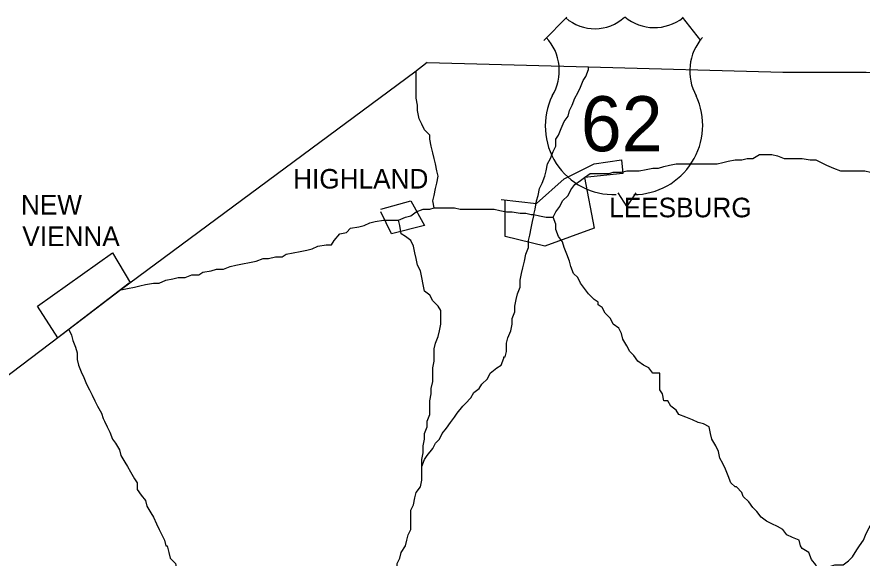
# Model space of a CAD drawing. Extents: x 0 to 34, y 0 to 22.
# Drawn here: x 3.578 to 4.42, y 18.911 to 19.45 of the extents above; entities that cross this region are included whole.
import ezdxf

# ---------------------------------------------------------------- set-up
doc = ezdxf.new("R2010")
doc.units = 0
doc.layers.add('Default', color=7, linetype='Continuous')

msp = doc.modelspace()

# ---------------------------------------------------------------- linework, layer by layer
at = {"layer": 'Default'}
for p, q in [((4.12627, 19.44935), (4.10326, 19.42634)), ((4.25971, 19.42634), (4.24131, 19.44935)), ((4.14382, 19.28966), (4.14928, 19.29375)), ((4.17689, 19.27449), (4.18609, 19.26069)), ((4.18609, 19.26069), (4.19529, 19.27449))]:
    msp.add_line(p, q, dxfattribs=at)
for points in [[(3.98703, 19.40419), (3.97476, 19.39464), (3.68162, 19.17786), (3.62981, 19.13832), (3.40076, 18.96516)], [(3.98703, 19.40419), (4.14791, 19.4001), (4.34152, 19.39464), (4.42469, 19.39464), (4.726, 19.38919), (4.75327, 19.38919)], [(3.99385, 19.25966), (3.99248, 19.26648), (3.99385, 19.27193), (3.99521, 19.27875), (3.99657, 19.2842), (3.99794, 19.29102), (3.99657, 19.29648), (3.99521, 19.30329), (3.99385, 19.30875), (3.99248, 19.3142), (3.99112, 19.32102), (3.98976, 19.32783), (3.98976, 19.33192), (3.9843, 19.33738), (3.98158, 19.34283), (3.97885, 19.34829), (3.97749, 19.35647), (3.97749, 19.36192), (3.97612, 19.36874), (3.97612, 19.37419), (3.97612, 19.38101), (3.97612, 19.38782), (3.97612, 19.39464), (3.97612, 19.39601), (3.97612, 19.39601)], [(4.09338, 19.25285), (4.09474, 19.2583), (4.0961, 19.26648), (4.09747, 19.27193), (4.09883, 19.27875), (4.10156, 19.2842), (4.10428, 19.29102), (4.10565, 19.29648), (4.10701, 19.30329), (4.10974, 19.30875), (4.11247, 19.31556), (4.11519, 19.32102), (4.11519, 19.32783), (4.11792, 19.33192), (4.12065, 19.33874), (4.12337, 19.34556), (4.12746, 19.35101), (4.12883, 19.35647), (4.13155, 19.36192), (4.13428, 19.36874), (4.13701, 19.37419), (4.13973, 19.37964), (4.14246, 19.38646), (4.14519, 19.39055), (4.14791, 19.39737), (4.14791, 19.4001)], [(4.21745, 19.2992), (4.2229, 19.30057), (4.22836, 19.30193), (4.23517, 19.30329), (4.24199, 19.30329), (4.24881, 19.30329), (4.25426, 19.30329), (4.26244, 19.30329), (4.2679, 19.30329), (4.27608, 19.30329), (4.28153, 19.30466), (4.28698, 19.30602), (4.2938, 19.30738), (4.30062, 19.30738), (4.30607, 19.30875), (4.31152, 19.30875), (4.31834, 19.31284), (4.32516, 19.31284), (4.33061, 19.31284), (4.33607, 19.31147), (4.34288, 19.30875), (4.34834, 19.30875), (4.3497, 19.30875)], [(4.3497, 19.30875), (4.35515, 19.30875), (4.36061, 19.30875), (4.36879, 19.30738), (4.37424, 19.30738), (4.3797, 19.30466), (4.38515, 19.30193), (4.39197, 19.2992), (4.39878, 19.29648), (4.40424, 19.29648), (4.40969, 19.29648), (4.41651, 19.29648), (4.42333, 19.29648), (4.42878, 19.29511), (4.4356, 19.29102), (4.44241, 19.28966), (4.44923, 19.28829), (4.45468, 19.28693), (4.4615, 19.28693), (4.46695, 19.28829), (4.46832, 19.28829)], [(4.06066, 19.26784), (4.0961, 19.26375), (4.12337, 19.28829), (4.15337, 19.30329), (4.18064, 19.30738), (4.182, 19.29375), (4.14382, 19.28966), (4.15337, 19.23921), (4.10428, 19.22149), (4.06475, 19.23103), (4.06475, 19.26648)], [(4.11247, 19.25012), (4.11519, 19.25557), (4.11928, 19.26103), (4.12201, 19.26648), (4.12746, 19.27193), (4.13019, 19.27739), (4.13428, 19.28284), (4.13973, 19.28693), (4.14382, 19.28966), (4.14928, 19.29375), (4.15473, 19.29375), (4.16155, 19.29375), (4.16837, 19.29375), (4.17246, 19.29511), (4.18064, 19.29511), (4.18609, 19.29648), (4.19427, 19.29648), (4.19836, 19.29648), (4.20518, 19.29784), (4.212, 19.2992), (4.21609, 19.2992), (4.21745, 19.2992)], [(3.94067, 19.2583), (3.97067, 19.26648), (3.9843, 19.24194), (3.95158, 19.23376), (3.94067, 19.25557)], [(3.9584, 19.24739), (3.96522, 19.25012), (3.97067, 19.25148), (3.97612, 19.25557), (3.98294, 19.2583), (3.98976, 19.2583), (3.99385, 19.25966), (3.99385, 19.25966)], [(3.9584, 19.24739), (3.96522, 19.25012), (3.97067, 19.25148), (3.97612, 19.25557), (3.98294, 19.2583), (3.98976, 19.2583), (3.99385, 19.25966), (3.99385, 19.25966)], [(3.99385, 19.25966), (4.00066, 19.25966), (4.00748, 19.25966), (4.0143, 19.25966), (4.01975, 19.2583), (4.02657, 19.2583), (4.03339, 19.2583), (4.03884, 19.2583), (4.04702, 19.2583), (4.05384, 19.2583), (4.05929, 19.25694), (4.06611, 19.25557), (4.07156, 19.25557), (4.07974, 19.25421), (4.0852, 19.25421), (4.09065, 19.25285), (4.09338, 19.25285)], [(4.06475, 19.11105), (4.06611, 19.1165), (4.06611, 19.12468), (4.06747, 19.13014), (4.0702, 19.13696), (4.07156, 19.14377), (4.07156, 19.14923), (4.07429, 19.15604), (4.07429, 19.1615), (4.07565, 19.16831), (4.07702, 19.17377), (4.07974, 19.18058), (4.07974, 19.1874), (4.08111, 19.19422), (4.08247, 19.19967), (4.08383, 19.20649), (4.0852, 19.21331), (4.08792, 19.22012), (4.08792, 19.22694), (4.08929, 19.23239), (4.09065, 19.23921), (4.09201, 19.24603), (4.09338, 19.25148), (4.09338, 19.25285)], [(4.09338, 19.25285), (4.09883, 19.25148), (4.10565, 19.25012), (4.11247, 19.25012)], [(4.15746, 19.16559), (4.15337, 19.16831), (4.14791, 19.17377), (4.14382, 19.17922), (4.13973, 19.18467), (4.13701, 19.19013), (4.13292, 19.19422), (4.13019, 19.20104), (4.12883, 19.20649), (4.1261, 19.21331), (4.12337, 19.22012), (4.12201, 19.22558), (4.11792, 19.23103), (4.11519, 19.23785), (4.11519, 19.2433), (4.11247, 19.25012), (4.11247, 19.25012)], [(3.80297, 19.20376), (3.80979, 19.20513), (3.8166, 19.20649), (3.82342, 19.20922), (3.82887, 19.20922), (3.83569, 19.21058), (3.84251, 19.21058), (3.8466, 19.21331), (3.85342, 19.21467), (3.86023, 19.21603), (3.86705, 19.2174), (3.8725, 19.21876), (3.87796, 19.22149), (3.88614, 19.22285), (3.89159, 19.22285), (3.89432, 19.22694), (3.89977, 19.23376), (3.90659, 19.23512), (3.91068, 19.23921), (3.91886, 19.24058), (3.92431, 19.24194), (3.92977, 19.24467), (3.93522, 19.24603), (3.9434, 19.24739), (3.94749, 19.24739), (3.95567, 19.24739), (3.9584, 19.24739), (3.9584, 19.24739)], [(4.00066, 19.15741), (3.99794, 19.1615), (3.99248, 19.16695), (3.98976, 19.1724), (3.9843, 19.17649), (3.98294, 19.18331), (3.98158, 19.19013), (3.98021, 19.19695), (3.97749, 19.2024), (3.97612, 19.20922), (3.97476, 19.21467), (3.9734, 19.22149), (3.97067, 19.22694), (3.96522, 19.23103), (3.96113, 19.23376), (3.95976, 19.24194), (3.9584, 19.24739), (3.9584, 19.24739)], [(3.68981, 19.18467), (3.61891, 19.13014), (3.59846, 19.1615), (3.67344, 19.21467), (3.69117, 19.18467)], [(3.68162, 19.17786), (3.68844, 19.17922), (3.69526, 19.18058), (3.70071, 19.18195), (3.70617, 19.18331), (3.71435, 19.18467), (3.7198, 19.18467), (3.72662, 19.1874), (3.73343, 19.18877), (3.73889, 19.19013), (3.74571, 19.19013), (3.75252, 19.19286), (3.75934, 19.19286), (3.76343, 19.19558), (3.77161, 19.19695), (3.77706, 19.19831), (3.78388, 19.19831), (3.7907, 19.20104), (3.79615, 19.2024), (3.80297, 19.20376), (3.80297, 19.20376)], [(4.2229, 19.06742), (4.22154, 19.07424), (4.21881, 19.07833), (4.21881, 19.08378), (4.21881, 19.08787), (4.21881, 19.09469), (4.212, 19.09469), (4.2079, 19.10014), (4.20245, 19.10287), (4.197, 19.10696), (4.19291, 19.11241), (4.18882, 19.1165), (4.18609, 19.12196), (4.182, 19.12877), (4.18064, 19.13423), (4.17791, 19.13968), (4.17246, 19.14377), (4.16973, 19.14923), (4.16428, 19.15468), (4.16155, 19.16013), (4.15746, 19.16286), (4.15746, 19.16559)], [(3.98158, 19.00198), (3.98158, 19.00879), (3.98294, 19.01561), (3.98294, 19.02243), (3.9843, 19.02924), (3.9843, 19.0347), (3.98703, 19.04152), (3.98703, 19.04697), (3.98976, 19.05379), (3.98976, 19.06197), (3.98976, 19.06742), (3.99112, 19.07424), (3.99112, 19.07969), (3.99248, 19.08651), (3.99248, 19.09333), (3.99248, 19.10014), (3.99385, 19.10696), (3.99385, 19.11241), (3.99385, 19.11923), (3.99521, 19.12468), (3.99794, 19.1315), (3.9993, 19.13696), (4.00066, 19.14377), (4.00066, 19.15059), (4.00066, 19.15604), (4.00066, 19.15741)], [(3.62981, 19.13832), (3.63254, 19.13286), (3.6339, 19.12741), (3.63663, 19.12059), (3.638, 19.11514), (3.638, 19.10832), (3.63936, 19.10287), (3.64209, 19.09605), (3.64481, 19.0906), (3.64754, 19.08378), (3.65027, 19.07833), (3.65299, 19.07287), (3.65572, 19.06742), (3.65845, 19.06197), (3.66254, 19.05515), (3.6639, 19.0497), (3.66526, 19.04697)], [(3.98158, 19.00198), (3.9843, 19.00879), (3.98703, 19.01288), (3.99248, 19.0197), (3.99521, 19.02515), (3.9993, 19.02924), (4.00203, 19.0347), (4.00612, 19.04015), (4.01021, 19.04561), (4.0143, 19.05106), (4.01703, 19.05515), (4.02248, 19.06197), (4.02521, 19.06469), (4.03066, 19.07015), (4.03339, 19.0756), (4.03884, 19.07969), (4.04157, 19.08378), (4.04702, 19.08924), (4.04975, 19.09469), (4.05657, 19.10014), (4.06066, 19.10287), (4.06338, 19.10969), (4.06338, 19.11105), (4.06475, 19.11105)], [(4.2938, 18.98153), (4.28971, 18.98562), (4.28698, 18.99243), (4.28426, 18.99925), (4.28153, 19.0047), (4.2788, 19.01016), (4.27744, 19.01697), (4.27471, 19.02243), (4.27062, 19.02924), (4.26926, 19.0347), (4.2679, 19.04152), (4.26244, 19.04424), (4.25699, 19.04561), (4.25153, 19.04833), (4.24472, 19.05106), (4.2379, 19.05379), (4.23517, 19.05788), (4.22972, 19.06197), (4.22699, 19.06742), (4.2229, 19.06742)], [(3.66526, 19.04697), (3.66799, 19.04152), (3.67072, 19.03606), (3.67344, 19.02924), (3.67617, 19.02515), (3.68026, 19.01834), (3.68162, 19.01288), (3.68571, 19.00607), (3.68844, 19.00198), (3.69117, 18.99652), (3.69526, 18.98971), (3.69799, 18.98562), (3.69799, 18.9788), (3.70208, 18.97334), (3.70617, 18.96789), (3.70753, 18.96244), (3.71162, 18.95562), (3.71435, 18.95153), (3.71707, 18.94471), (3.7198, 18.93926), (3.72253, 18.93381), (3.72525, 18.92835), (3.72662, 18.9229), (3.72798, 18.9229)], [(3.95704, 18.89836), (3.95704, 18.90517), (3.95976, 18.91063), (3.96113, 18.91608), (3.96522, 18.9229), (3.96658, 18.92835), (3.96794, 18.93381), (3.97067, 18.93926), (3.97067, 18.94744), (3.97067, 18.95289), (3.97067, 18.95835), (3.9734, 18.9638), (3.97476, 18.97062), (3.97612, 18.97607), (3.98021, 18.98153), (3.98158, 18.98834), (3.98158, 18.99516), (3.98158, 19.00198), (3.98158, 19.00198)], [(4.37697, 18.89836), (4.37424, 18.90381), (4.37015, 18.90926), (4.36743, 18.91608), (4.36061, 18.92017), (4.35924, 18.9229), (4.35788, 18.92835), (4.35106, 18.93108), (4.34561, 18.93381), (4.34152, 18.93926), (4.33607, 18.94199), (4.33061, 18.94471), (4.32516, 18.94744), (4.31971, 18.95153), (4.31562, 18.95698), (4.31152, 18.96107), (4.30743, 18.96653), (4.30198, 18.97198), (4.30062, 18.97607), (4.29516, 18.98153), (4.2938, 18.98153), (4.2938, 18.98153)], [(4.37697, 18.89836), (4.38242, 18.89972), (4.38924, 18.90245), (4.39333, 18.90381), (4.40151, 18.90381), (4.40696, 18.9079), (4.41105, 18.91199), (4.41514, 18.91881), (4.41787, 18.9229), (4.42196, 18.92835), (4.42469, 18.93517), (4.42742, 18.94062), (4.43151, 18.94744), (4.43423, 18.95289), (4.43696, 18.95698), (4.43969, 18.9638), (4.44241, 18.96925), (4.4465, 18.97607), (4.44923, 18.98153), (4.44923, 18.98425)], [(3.72798, 18.9229), (3.72934, 18.91608), (3.73071, 18.91063), (3.73616, 18.90517), (3.73752, 18.89836), (3.73889, 18.8929), (3.73889, 18.88745), (3.73889, 18.882), (3.73889, 18.87518), (3.73889, 18.86836), (3.74025, 18.86291), (3.74162, 18.85745), (3.74434, 18.85064), (3.74571, 18.84518), (3.74707, 18.84109), (3.74707, 18.84109)]]:
    msp.add_lwpolyline(points, dxfattribs=at)
for centre, radius, start, end in [((4.15402, 19.48184), 0.04388, 228.71859, 312.45521), ((4.21349, 19.48556), 0.04643, 230.45249, 307.79333), ((4.0704, 19.39633), 0.04829, 328.44295, 43.21082), ((4.29922, 19.39583), 0.05055, 138.39443, 209.34239), ((4.17307, 19.34113), 0.06842, 154.0604, 271.92319), ((4.1925, 19.34185), 0.06913, 270.37171, 24.99189)]:
    msp.add_arc(centre, radius, start, end, dxfattribs=at)

# ---------------------------------------------------------------- texts
for s, height, p in [('62', 0.05486, (4.14007, 19.3159)), ('HIGHLAND', 0.019502, (3.85342, 19.27875)), ('NEW', 0.019502, (3.58209, 19.25285)), ('LEESBURG', 0.019502, (4.16837, 19.25012)), ('VIENNA', 0.019502, (3.58346, 19.22149))]:
    msp.add_text(s, height=height, dxfattribs=at).set_placement(p)

doc.saveas('drawing.dxf')
